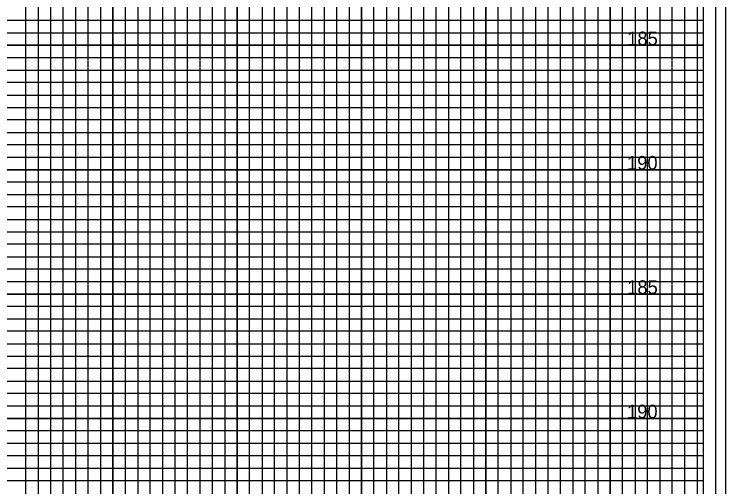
# Model space of a CAD drawing. Extents: x -4 to 103, y -2 to 6583.
# Drawn here: x 74.78 to 103.4, y 669.68 to 688.68 of the extents above; entities that cross this region are included whole.
import ezdxf

# ---------------------------------------------------------------- set-up
doc = ezdxf.new("R2010")
doc.units = 0
for name, color, linetype in [('Prop XS Elevation Labels', 7, 'Continuous'), ('Sheet Cross Section CELL', 7, 'Continuous'), ('Sheet Cross Section Grid Major CELL', 7, 'Continuous'), ('Sheet Cross Section Grid Middle CELL', 7, 'Continuous'), ('Sheet DOT Grid CELL', 7, 'Continuous'), ('Sheet Plot Border Inside CELL', 7, 'Continuous'), ('Sheet Plot Border Outside CELL', 7, 'Continuous')]:
    doc.layers.add(name, color=color, linetype=linetype)

msp = doc.modelspace()

# ---------------------------------------------------------------- linework, layer by layer
at = {"layer": 'Sheet Cross Section CELL'}
msp.add_lwpolyline([(102.5, 702.425), (0, 702.425), (0, 637.425), (102.5, 637.425)], close=True, dxfattribs=at)
at = {"layer": 'Sheet Cross Section Grid Major CELL'}
for points in [[(91.25, 637.425), (91.25, 700.85), (93.75, 700.85), (93.75, 637.425)], [(96.25, 637.425), (96.25, 700.85), (98.75, 700.85), (98.75, 637.425)], [(101.25, 637.425), (101.25, 700.85)], [(76.25, 637.425), (76.25, 699.425), (78.75, 699.425), (78.75, 637.425)], [(81.25, 637.425), (81.25, 699.425), (83.75, 699.425), (83.75, 637.425)], [(86.25, 637.425), (86.25, 699.425), (88.75, 699.425), (88.75, 637.425)], [(0, 684.925), (102.5, 684.925), (102.5, 687.425), (0, 687.425)], [(0, 679.925), (102.5, 679.925), (102.5, 682.425), (0, 682.425)], [(0, 674.925), (102.5, 674.925), (102.5, 677.425), (0, 677.425)], [(0, 669.925), (102.5, 669.925), (102.5, 672.425), (0, 672.425)]]:
    msp.add_lwpolyline(points, dxfattribs=at)
at = {"layer": 'Sheet Cross Section Grid Middle CELL'}
for points in [[(90.25, 637.425), (90.25, 700.85), (90.75, 700.85), (90.75, 637.425)], [(91.75, 637.425), (91.75, 700.85), (92.25, 700.85), (92.25, 637.425)], [(92.75, 637.425), (92.75, 700.85), (93.25, 700.85), (93.25, 637.425)], [(94.25, 637.425), (94.25, 700.85), (94.75, 700.85), (94.75, 637.425)], [(95.25, 637.425), (95.25, 700.85), (95.75, 700.85), (95.75, 637.425)], [(96.75, 637.425), (96.75, 700.85), (97.25, 700.85), (97.25, 637.425)], [(97.75, 637.425), (97.75, 700.85), (98.25, 700.85), (98.25, 637.425)], [(99.25, 637.425), (99.25, 700.85), (99.75, 700.85), (99.75, 637.425)], [(100.25, 637.425), (100.25, 700.85)], [(100.25, 700.85), (100.75, 700.85), (100.75, 637.425), (101.75, 637.425), (101.75, 700.85), (102.25, 700.85), (102.25, 637.425)], [(75.25, 637.425), (75.25, 699.425), (75.75, 699.425), (75.75, 637.425)], [(76.75, 637.425), (76.75, 699.425), (77.25, 699.425), (77.25, 637.425)], [(77.75, 637.425), (77.75, 699.425), (78.25, 699.425), (78.25, 637.425)], [(79.25, 637.425), (79.25, 699.425), (79.75, 699.425), (79.75, 637.425)], [(80.25, 637.425), (80.25, 699.425), (80.75, 699.425), (80.75, 637.425)], [(81.75, 637.425), (81.75, 699.425), (82.25, 699.425), (82.25, 637.425)], [(82.75, 637.425), (82.75, 699.425), (83.25, 699.425), (83.25, 637.425)], [(84.25, 637.425), (84.25, 699.425), (84.75, 699.425), (84.75, 637.425)], [(85.25, 637.425), (85.25, 699.425), (85.75, 699.425), (85.75, 637.425)], [(86.75, 637.425), (86.75, 699.425), (87.25, 699.425), (87.25, 637.425)], [(87.75, 637.425), (87.75, 699.425), (88.25, 699.425), (88.25, 637.425)], [(89.25, 637.425), (89.25, 699.425), (89.75, 699.425), (89.75, 637.425)], [(0, 687.925), (102.5, 687.925), (102.5, 688.425), (0, 688.425)], [(0, 686.425), (102.5, 686.425), (102.5, 686.925), (0, 686.925)], [(0, 685.425), (102.5, 685.425), (102.5, 685.925), (0, 685.925)], [(0, 683.925), (102.5, 683.925), (102.5, 684.425), (0, 684.425)], [(0, 682.925), (102.5, 682.925), (102.5, 683.425), (0, 683.425)], [(0, 681.425), (102.5, 681.425), (102.5, 681.925), (0, 681.925)], [(0, 680.425), (102.5, 680.425), (102.5, 680.925), (0, 680.925)], [(0, 678.925), (102.5, 678.925), (102.5, 679.425), (0, 679.425)], [(0, 677.925), (102.5, 677.925), (102.5, 678.425), (0, 678.425)], [(0, 676.425), (102.5, 676.425), (102.5, 676.925), (0, 676.925)], [(0, 675.425), (102.5, 675.425), (102.5, 675.925), (0, 675.925)], [(0, 673.925), (102.5, 673.925), (102.5, 674.425), (0, 674.425)], [(0, 672.925), (102.5, 672.925), (102.5, 673.425), (0, 673.425)], [(0, 671.425), (102.5, 671.425), (102.5, 671.925), (0, 671.925)], [(0, 670.425), (102.5, 670.425), (102.5, 670.925), (0, 670.925)]]:
    msp.add_lwpolyline(points, dxfattribs=at)
at = {"layer": 'Sheet DOT Grid CELL'}
for p, q in [((91.25, 637.425), (91.25, 700.85)), ((93.75, 637.425), (93.75, 700.85)), ((96.25, 637.425), (96.25, 700.85)), ((98.75, 637.425), (98.75, 700.85)), ((101.25, 637.425), (101.25, 700.85)), ((76.25, 637.425), (76.25, 699.425)), ((78.75, 637.425), (78.75, 699.425)), ((81.25, 637.425), (81.25, 699.425)), ((83.75, 637.425), (83.75, 699.425)), ((86.25, 637.425), (86.25, 699.425)), ((88.75, 637.425), (88.75, 699.425)), ((0, 687.425), (102.5, 687.425)), ((0, 684.925), (102.5, 684.925)), ((0, 682.425), (102.5, 682.425)), ((0, 679.925), (102.5, 679.925)), ((0, 677.425), (102.5, 677.425)), ((0, 674.925), (102.5, 674.925)), ((0, 672.425), (102.5, 672.425)), ((0, 669.925), (102.5, 669.925))]:
    msp.add_line(p, q, dxfattribs=at)
at = {"layer": 'Sheet Plot Border Inside CELL'}
msp.add_lwpolyline([(103, 703.425), (-2.8, 703.425), (-2.8, 636.425), (103, 636.425)], close=True, dxfattribs=at)
at = {"layer": 'Sheet Plot Border Outside CELL'}
msp.add_lwpolyline([(103.4, 704.825), (-3.5, 704.825), (-3.5, 635), (103.4, 635)], close=True, dxfattribs=at)

# ---------------------------------------------------------------- texts
at = {"layer": 'Prop XS Elevation Labels'}
for s, p in [('185', (99.438, 687.425)), ('190', (99.43, 682.425)), ('185', (99.438, 677.425)), ('190', (99.43, 672.425))]:
    msp.add_text(s, height=0.55, dxfattribs=at).set_placement(p)

doc.saveas('drawing.dxf')
